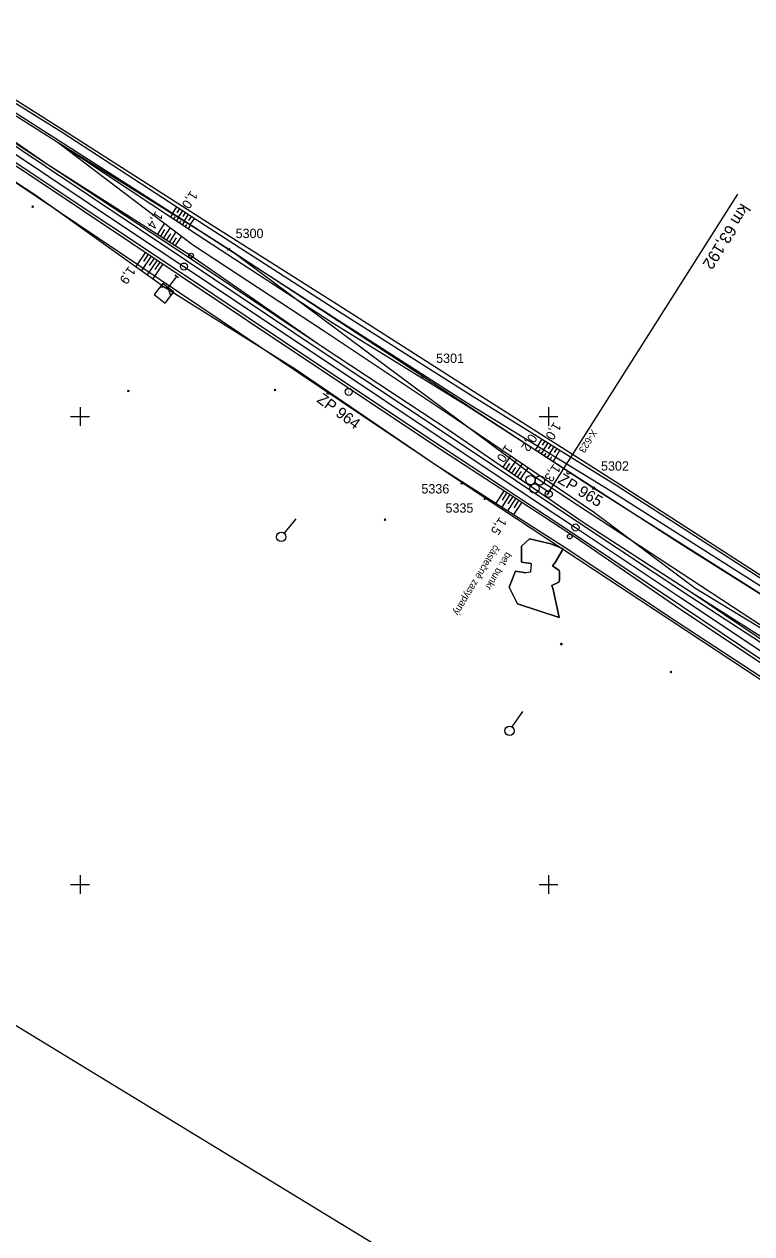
# Model space of a CAD drawing. Extents: x -804899 to -803847, y -1165742 to -1164942.
# Drawn here: x -804511.9 to -804356.6, y -1165474.6 to -1165216.2 of the extents above; entities that cross this region are included whole.
import ezdxf

# ---------------------------------------------------------------- set-up
doc = ezdxf.new("R2010")
doc.units = 0
for name, color, linetype in [('0381KM061-064P - Vrstva 1', 7, 'Continuous'), ('0381KM061-064P - Vrstva 23', 7, 'Continuous'), ('0381KM061-064P - Vrstva 36', 7, 'Continuous'), ('0381KM061-064P - Vrstva 4', 7, 'Continuous'), ('0381KM061-064P - Vrstva 48', 7, 'Continuous'), ('0381KM061-064P - Vrstva 49', 7, 'Continuous'), ('0381KM061-064P - Vrstva 51', 7, 'Continuous'), ('0381KM061-064P - Vrstva 55', 7, 'Continuous'), ('0381KM061-064P - Vrstva 7', 7, 'Continuous'), ('0381KM061-064P - Vrstva 8', 7, 'Continuous'), ('formát', 7, 'Continuous'), ('krizky_1000 - Vrstva 1', 7, 'Continuous'), ('szdc - hran DP', 7, 'Continuous'), ('szdc - szdc_cislo', 7, 'Continuous'), ('szdc - szdc_krizek', 7, 'Continuous'), ('vyt_sit - stávající', 7, 'Continuous')]:
    doc.layers.add(name, color=color, linetype=linetype)

msp = doc.modelspace()

# ---------------------------------------------------------------- linework, layer by layer
at = {"layer": '0381KM061-064P - Vrstva 1'}
msp.add_lwpolyline([(-804619.36, -1165173.74), (-804594.78, -1165190.05), (-804577, -1165201.91), (-804561.16, -1165212.47), (-804538.32, -1165227.67), (-804515.3, -1165243.02), (-804489.41, -1165260.27), (-804477.81, -1165268), (-804447.6, -1165288.14), (-804422.03, -1165305.2), (-804398.19, -1165321.09), (-804394.24, -1165323.73), (-804371.85, -1165338.65), (-804349.9, -1165353.29), (-804326.64, -1165368.8), (-804303.84, -1165384.01), (-804280.33, -1165399.7), (-804257.04, -1165415.23), (-804233.85, -1165430.69)], dxfattribs=at)
at = {"layer": '0381KM061-064P - Vrstva 23'}
msp.add_lwpolyline([(-804404.03, -1165326.13), (-804405.8, -1165327.74), (-804405.76, -1165331.16), (-804403.73, -1165331.39), (-804403.83, -1165333.25), (-804404.81, -1165333.4), (-804407.08, -1165333.06), (-804408.38, -1165336.47), (-804406.6, -1165340), (-804397.73, -1165342.97), (-804399.04, -1165336.98), (-804399.28, -1165336.09), (-804397.81, -1165335.38), (-804397.64, -1165335), (-804397.65, -1165333.2), (-804397.7, -1165332.91), (-804399.15, -1165331.95), (-804398.58, -1165331.24), (-804396.84, -1165328.29), (-804399.49, -1165327.23), (-804404.03, -1165326.13)], dxfattribs=at)
at = {"layer": '0381KM061-064P - Vrstva 36'}
for p, q in [((-804456.41, -1165324.98), (-804453.88, -1165321.88)), ((-804457.04, -1165325.75), (-804457.04, -1165325.75)), ((-804407.75, -1165366.33), (-804405.5, -1165363.02)), ((-804408.31, -1165367.16), (-804408.31, -1165367.16))]:
    msp.add_line(p, q, dxfattribs=at)
for centre in [(-804457.04, -1165325.75), (-804408.31, -1165367.16)]:
    msp.add_circle(centre, 1, dxfattribs=at)
at = {"layer": '0381KM061-064P - Vrstva 4'}
for points in [[(-804755.73, -1165115.93), (-804748.17, -1165116.91), (-804721.25, -1165123.25), (-804698.66, -1165130.22), (-804681.33, -1165136.99), (-804671.47, -1165141.65), (-804648.84, -1165153.36), (-804638.11, -1165160.03), (-804624.48, -1165168.7), (-804602.56, -1165183.07), (-804574.47, -1165201.72), (-804542.72, -1165222.84), (-804507.36, -1165246.55), (-804477.08, -1165266.82), (-804448.75, -1165285.88), (-804421.18, -1165304.15), (-804392.89, -1165323.09), (-804369.85, -1165338.37), (-804348.86, -1165352.04), (-804325.13, -1165367.98), (-804299.32, -1165385.27), (-804266.05, -1165407.31), (-804234.28, -1165428.6)], [(-804755.73, -1165115.93), (-804748.03, -1165116.49), (-804721.05, -1165122.36), (-804698.44, -1165129.77), (-804680.98, -1165136.5), (-804671.21, -1165140.89), (-804648.42, -1165152.46), (-804637.55, -1165159.43), (-804624.04, -1165168.29), (-804602.25, -1165182.38), (-804573.74, -1165201.2), (-804542.46, -1165222.56), (-804507.06, -1165246.03), (-804476.47, -1165266.24), (-804448.31, -1165285.08), (-804421.02, -1165303.1), (-804392.59, -1165322.59), (-804369.41, -1165337.65), (-804348.68, -1165351.59), (-804324.76, -1165367.42), (-804298.9, -1165384.42), (-804265.65, -1165406.5), (-804234.05, -1165428.04)], [(-804626.64, -1165171.43), (-804605.18, -1165186.34), (-804576.91, -1165204.69), (-804544.69, -1165226.09), (-804509.35, -1165249.3), (-804478.87, -1165269.77), (-804450.06, -1165288.98), (-804422.82, -1165307.11), (-804394.42, -1165325.66), (-804371.77, -1165341.24), (-804350.46, -1165355.38), (-804326.73, -1165371.34), (-804301.47, -1165388.34), (-804268.3, -1165410.72), (-804235.74, -1165432.01)], [(-804576.36, -1165204.15), (-804544.19, -1165225.52), (-804508.95, -1165249), (-804478.52, -1165269.18), (-804449.67, -1165288.56), (-804422.62, -1165306.58), (-804394.22, -1165325.33), (-804371.37, -1165340.61), (-804350.54, -1165354.66), (-804326.31, -1165370.81), (-804300.9, -1165387.72), (-804267.8, -1165409.92), (-804235.52, -1165431.44)]]:
    msp.add_lwpolyline(points, dxfattribs=at)
at = {"layer": '0381KM061-064P - Vrstva 48'}
for p, q in [((-804480.29, -1165256.71), (-804479.34, -1165255.26)), ((-804479.28, -1165256.53), (-804478.71, -1165255.67)), ((-804479.02, -1165257.51), (-804478.08, -1165256.08)), ((-804478.01, -1165257.34), (-804477.46, -1165256.49)), ((-804481.97, -1165258.76), (-804483.45, -1165261.08)), ((-804480.25, -1165256.74), (-804480.67, -1165257.37)), ((-804479.78, -1165257.4), (-804480.04, -1165257.79)), ((-804478.97, -1165257.53), (-804479.42, -1165258.2)), ((-804478.52, -1165258.2), (-804478.79, -1165258.61)), ((-804477.7, -1165258.33), (-804478.16, -1165259.03)), ((-804477.74, -1165258.3), (-804476.83, -1165256.9)), ((-804477.25, -1165259.01), (-804477.54, -1165259.44)), ((-804476.43, -1165259.12), (-804476.91, -1165259.86)), ((-804476.74, -1165258.14), (-804476.2, -1165257.3)), ((-804476.47, -1165259.09), (-804475.57, -1165257.71)), ((-804481.95, -1165260.12), (-804482.82, -1165261.48)), ((-804480.77, -1165259.67), (-804482.18, -1165261.89)), ((-804480.72, -1165260.99), (-804481.55, -1165262.29)), ((-804479.57, -1165260.57), (-804480.92, -1165262.69)), ((-804478.37, -1165261.48), (-804479.66, -1165263.5)), ((-804479.5, -1165261.86), (-804480.29, -1165263.1)), ((-804486.06, -1165264.95), (-804488.11, -1165268)), ((-804484.82, -1165265.78), (-804486.89, -1165268.87)), ((-804485.44, -1165265.36), (-804486.47, -1165266.9)), ((-804483.57, -1165266.62), (-804485.67, -1165269.74)), ((-804484.19, -1165266.2), (-804485.24, -1165267.75)), ((-804482.32, -1165267.45), (-804484.45, -1165270.61)), ((-804482.95, -1165267.04), (-804484, -1165268.61)), ((-804402.3, -1165306.36), (-804401.37, -1165304.86)), ((-804401.29, -1165306.16), (-804400.73, -1165305.26)), ((-804401.02, -1165307.14), (-804400.09, -1165305.66)), ((-804402.31, -1165306.35), (-804402.82, -1165307.15)), ((-804401.88, -1165307.07), (-804402.19, -1165307.55)), ((-804401.03, -1165307.14), (-804401.56, -1165307.96)), ((-804400.6, -1165307.87), (-804400.93, -1165308.37)), ((-804399.75, -1165307.92), (-804400.3, -1165308.78)), ((-804400.01, -1165306.94), (-804399.46, -1165306.05)), ((-804399.74, -1165307.93), (-804398.82, -1165306.45)), ((-804398.73, -1165307.73), (-804398.18, -1165306.84)), ((-804398.46, -1165308.71), (-804397.55, -1165307.24)), ((-804409.69, -1165310.87), (-804408.04, -1165308.45)), ((-804409.07, -1165311.29), (-804408.24, -1165310.08)), ((-804408.45, -1165311.72), (-804406.79, -1165309.3)), ((-804407.22, -1165312.57), (-804405.55, -1165310.14)), ((-804399.33, -1165308.66), (-804399.67, -1165309.19)), ((-804398.47, -1165308.71), (-804399.04, -1165309.59)), ((-804407.84, -1165312.14), (-804407, -1165310.93)), ((-804406.6, -1165312.99), (-804405.76, -1165311.77)), ((-804405.98, -1165313.41), (-804404.31, -1165310.98)), ((-804411.18, -1165318.55), (-804409.42, -1165315.86)), ((-804409.92, -1165319.36), (-804408.16, -1165316.68)), ((-804409.84, -1165317.89), (-804408.79, -1165316.27)), ((-804408.65, -1165320.17), (-804406.91, -1165317.5)), ((-804408.58, -1165318.7), (-804407.54, -1165317.09)), ((-804407.39, -1165320.98), (-804405.65, -1165318.32)), ((-804407.32, -1165319.51), (-804406.28, -1165317.91))]:
    msp.add_line(p, q, dxfattribs=at)
at = {"layer": '0381KM061-064P - Vrstva 49'}
for p, q in [((-804509.94, -1165255.38), (-804510.3, -1165255.03)), ((-804509.94, -1165255.03), (-804510.3, -1165255.38)), ((-804489.49, -1165294.74), (-804489.84, -1165294.38)), ((-804489.49, -1165294.38), (-804489.84, -1165294.74)), ((-804458.23, -1165294.57), (-804458.58, -1165294.21)), ((-804458.23, -1165294.21), (-804458.58, -1165294.57)), ((-804434.74, -1165322.21), (-804435.09, -1165321.86)), ((-804434.74, -1165321.86), (-804435.09, -1165322.21)), ((-804397.06, -1165348.83), (-804397.41, -1165348.47)), ((-804397.06, -1165348.47), (-804397.41, -1165348.83)), ((-804373.68, -1165354.74), (-804374.04, -1165354.39)), ((-804373.68, -1165354.39), (-804374.04, -1165354.74))]:
    msp.add_line(p, q, dxfattribs=at)
for points in [[(-804668.09, -1165135.13), (-804646.08, -1165148.91), (-804635.34, -1165155.79), (-804621.98, -1165164.4), (-804599.68, -1165178.86), (-804570.23, -1165197.63), (-804539.04, -1165217.4), (-804503.79, -1165239.32), (-804473.21, -1165259.25), (-804445.02, -1165277.37), (-804416.3, -1165295.6), (-804385.23, -1165314.87), (-804342.84, -1165342.16), (-804322.16, -1165355.5), (-804292.15, -1165374.6), (-804262.58, -1165393.44), (-804234.25, -1165411.43)], [(-804668.53, -1165136.56), (-804646.51, -1165150.38), (-804635.75, -1165157.19), (-804622.88, -1165165.28), (-804600.74, -1165180), (-804571.06, -1165199.05), (-804539.91, -1165219.23), (-804504.85, -1165241.38), (-804474.07, -1165260.59), (-804445.75, -1165278.86), (-804417.38, -1165297.08), (-804386.13, -1165316.29), (-804343.68, -1165343.22), (-804323.05, -1165356.81), (-804293.41, -1165375.48), (-804263.45, -1165394.43), (-804234.68, -1165412.78)], [(-804651.73, -1165158.22), (-804641.24, -1165165.82), (-804629.21, -1165174.28), (-804606.38, -1165188.59), (-804578.69, -1165207.38), (-804546.55, -1165228.41), (-804509.4, -1165252.77), (-804482.02, -1165272.35), (-804454.07, -1165289.87), (-804424.02, -1165310.32)], [(-804621.79, -1165169), (-804602.1, -1165181.9), (-804573.29, -1165200.8), (-804541.65, -1165222.05), (-804507.06, -1165246.03), (-804476.55, -1165265.48), (-804448.31, -1165285.08)], [(-804576.91, -1165204.69), (-804544.69, -1165226.09), (-804509.35, -1165249.3), (-804478.87, -1165269.77), (-804450.06, -1165288.98), (-804422.82, -1165307.11), (-804394.42, -1165325.66), (-804371.77, -1165341.24), (-804350.46, -1165355.38), (-804326.73, -1165371.34), (-804301.47, -1165388.34), (-804268.3, -1165410.72), (-804235.74, -1165432.01)], [(-804504.85, -1165241.38), (-804475.98, -1165263.3)], [(-804504.85, -1165241.38), (-804474.97, -1165261.14)], [(-804474.97, -1165261.14), (-804446.16, -1165279.93), (-804417.55, -1165297.62), (-804371.56, -1165327.37), (-804344.89, -1165344.14), (-804323.3, -1165357.63), (-804293.83, -1165376.15), (-804263.84, -1165395.04), (-804235.23, -1165413.58)], [(-804475.98, -1165263.3), (-804448.01, -1165281.64), (-804419.88, -1165300.43), (-804390.2, -1165320.54), (-804368.79, -1165336.61), (-804347.55, -1165349.48), (-804323.92, -1165365.2), (-804298.45, -1165381.67), (-804264.49, -1165403.75), (-804232.5, -1165426.01)], [(-804448.31, -1165285.08), (-804421.02, -1165303.1), (-804392.59, -1165322.59), (-804369.41, -1165337.65)], [(-804424.02, -1165310.32), (-804397.08, -1165327.6), (-804372.3, -1165344.03), (-804352.55, -1165356.96), (-804329.59, -1165372.88)], [(-804403.73, -1165331.39), (-804405.76, -1165331.16), (-804405.8, -1165327.74), (-804404.03, -1165326.13), (-804399.49, -1165327.23), (-804396.84, -1165328.29), (-804398.58, -1165331.24)], [(-804403.73, -1165331.39), (-804403.83, -1165333.25), (-804404.81, -1165333.4)], [(-804398.58, -1165331.24), (-804399.15, -1165331.95), (-804397.7, -1165332.91), (-804397.65, -1165333.2), (-804397.64, -1165335), (-804397.81, -1165335.38), (-804399.28, -1165336.09), (-804399.04, -1165336.98)], [(-804399.04, -1165336.98), (-804397.73, -1165342.97), (-804406.6, -1165340), (-804408.38, -1165336.47), (-804407.08, -1165333.06), (-804404.81, -1165333.4)], [(-804369.41, -1165337.65), (-804350.13, -1165349.85)]]:
    msp.add_lwpolyline(points, dxfattribs=at)
at = {"layer": '0381KM061-064P - Vrstva 51'}
msp.add_lwpolyline([(-804728.9, -1165105.9), (-804711.54, -1165108.67), (-804704.35, -1165111.8), (-804683.69, -1165124.09), (-804676.95, -1165128.43), (-804667.36, -1165134.41), (-804645.71, -1165148.3), (-804634.7, -1165155.23), (-804621.63, -1165163.62), (-804599.19, -1165178.23), (-804569.67, -1165197.16), (-804538.42, -1165216.77), (-804503.41, -1165238.94), (-804472.82, -1165258.55), (-804444.57, -1165276.4), (-804415.82, -1165294.73), (-804384.7, -1165314.57), (-804342.59, -1165341.72), (-804321.8, -1165355.02), (-804291.77, -1165374.22), (-804262.45, -1165392.96)], dxfattribs=at)
at = {"layer": '0381KM061-064P - Vrstva 55'}
msp.add_lwpolyline([(-804468.27, -1165264.32), (-804426.86, -1165291.43), (-804390.35, -1165315.35), (-804348.41, -1165341.86), (-804327.45, -1165354.94), (-804302.94, -1165371.26), (-804261.01, -1165397.26), (-804213.5, -1165427.44), (-804191.69, -1165441.88), (-804177.28, -1165451.4), (-804169.73, -1165458.18), (-804172.29, -1165470.42), (-804193.11, -1165453.43), (-804217.51, -1165435.77), (-804323.51, -1165365.07), (-804402.46, -1165313.29)], close=True, dxfattribs=at)
at = {"layer": '0381KM061-064P - Vrstva 7'}
for p, q in [((-804476.35, -1165265.63), (-804476.26, -1165265.69)), ((-804481.17, -1165272.51), (-804479.35, -1165270.13)), ((-804478.95, -1165270.43), (-804479.75, -1165269.83)), ((-804395.51, -1165325.63), (-804395.43, -1165325.69))]:
    msp.add_line(p, q, dxfattribs=at)
for points in [[(-804481.17, -1165272.51), (-804482.36, -1165271.6), (-804484.18, -1165273.99), (-804481.8, -1165275.81), (-804479.98, -1165273.42), (-804481.17, -1165272.51)], [(-804480.59, -1165274.22), (-804481.17, -1165272.51), (-804482.97, -1165272.4)]]:
    msp.add_lwpolyline(points, dxfattribs=at)
for centre, radius in [((-804476.3, -1165265.66), 0.5), ((-804477.81, -1165268), 0.75), ((-804394.24, -1165323.73), 0.75), ((-804395.47, -1165325.66), 0.5)]:
    msp.add_circle(centre, radius, dxfattribs=at)
at = {"layer": '0381KM061-064P - Vrstva 8'}
for p, q in [((-804399.91, -1165316.21), (-804359.62, -1165252.51)), ((-804399.91, -1165316.21), (-804402.41, -1165314.55)), ((-804400.33, -1165316.84), (-804399.49, -1165315.59))]:
    msp.add_line(p, q, dxfattribs=at)
for centre in [(-804403.82, -1165313.61), (-804401.85, -1165313.72), (-804402.96, -1165315.38)]:
    msp.add_circle(centre, 1, dxfattribs=at)
at = {"layer": 'formát'}
msp.add_line((-804360.64, -1165523.44), (-804898.57, -1165195.52), dxfattribs=at)
at = {"layer": 'krizky_1000 - Vrstva 1'}
for points in [[(-804502, -1165300), (-804498, -1165300)], [(-804500, -1165298), (-804500, -1165302)], [(-804402, -1165300), (-804398, -1165300)], [(-804400, -1165298), (-804400, -1165302)], [(-804500, -1165398), (-804500, -1165402)], [(-804400, -1165398), (-804400, -1165402)], [(-804502, -1165400), (-804498, -1165400)], [(-804402, -1165400), (-804398, -1165400)]]:
    msp.add_lwpolyline(points, dxfattribs=at)
at = {"layer": 'szdc - hran DP'}
for p, q in [((-804418.46, -1165314.18), (-804552.85, -1165223.84)), ((-804519.76, -1165231.32), (-804468.27, -1165264.32)), ((-804468.27, -1165264.32), (-804426.86, -1165291.43)), ((-804426.86, -1165291.43), (-804390.35, -1165315.35)), ((-804413.53, -1165317.49), (-804418.46, -1165314.18)), ((-804390.35, -1165315.35), (-804348.41, -1165341.86)), ((-804272.3, -1165410.7), (-804413.53, -1165317.49))]:
    msp.add_line(p, q, dxfattribs=at)
at = {"layer": 'szdc - szdc_krizek'}
for p, q in [((-804468.01, -1165264.58), (-804468.54, -1165264.05)), ((-804468.54, -1165264.58), (-804468.01, -1165264.05)), ((-804426.59, -1165291.7), (-804427.13, -1165291.17)), ((-804427.13, -1165291.7), (-804426.59, -1165291.17)), ((-804418.2, -1165314.45), (-804418.73, -1165313.92)), ((-804418.73, -1165314.45), (-804418.2, -1165313.92)), ((-804390.08, -1165315.61), (-804390.62, -1165315.08)), ((-804390.62, -1165315.61), (-804390.08, -1165315.08)), ((-804413.27, -1165317.76), (-804413.8, -1165317.23)), ((-804413.8, -1165317.76), (-804413.27, -1165317.23))]:
    msp.add_line(p, q, dxfattribs=at)
at = {"layer": 'vyt_sit - stávající'}
for p, q in [((-804442.7, -1165294.74), (-804442.61, -1165294.8)), ((-804399.99, -1165316.55), (-804399.91, -1165316.61))]:
    msp.add_line(p, q, dxfattribs=at)
for centre in [(-804442.66, -1165294.77), (-804399.95, -1165316.58)]:
    msp.add_circle(centre, 0.756, dxfattribs=at)

# ---------------------------------------------------------------- texts
at = {"layer": '0381KM061-064P - Vrstva 23'}
for s, p in [('částečně zasypaný', (-804411.6, -1165327.33)), ('bet. bunkr', (-804409.02, -1165328.87))]:
    msp.add_text(s, height=1.5, rotation=239.0639, dxfattribs=at).set_placement(p)
at = {"layer": '0381KM061-064P - Vrstva 48'}
for s, rotation, p in [('1,0', 236.9037, (-804476.36, -1165251.68)), ('1,4', 237.4781, (-804483.81, -1165256.02)), ('1,9', 236.1009, (-804489.6, -1165267.8)), ('1,0', 238.1936, (-804398.79, -1165301.06)), ('0,2', 237.1025, (-804403.93, -1165303.54)), ('1,0', 235.8765, (-804409.09, -1165305.87)), ('1,3', 235.5742, (-804398.89, -1165310.02)), ('1,5', 236.8458, (-804410.41, -1165321.38))]:
    msp.add_text(s, height=2, rotation=rotation, dxfattribs=at).set_placement(p)
at = {"layer": '0381KM061-064P - Vrstva 8'}
for s, height, rotation, p in [('km 63,192', 2.5, 237.6925, (-804358.88, -1165254.34)), ('X-623', 1.5, 237.6921, (-804390.75, -1165302.64))]:
    msp.add_text(s, height=height, rotation=rotation, dxfattribs=at).set_placement(p)
at = {"layer": 'szdc - szdc_cislo'}
for s, p in [('5300', (-804466.79, -1165261.92)), ('5301', (-804423.99, -1165288.59)), ('5302', (-804388.79, -1165311.59)), ('5336', (-804427.13, -1165316.47)), ('5335', (-804421.99, -1165320.57))]:
    msp.add_text(s, height=2, dxfattribs=at).set_placement(p)
at = {"layer": 'vyt_sit - stávající'}
for s, rotation, p in [('ŽP 964', 323.5611, (-804449.64, -1165296.77)), ('ŽP 965', 328.5611, (-804398.21, -1165314.06))]:
    msp.add_text(s, height=2.4, rotation=rotation, dxfattribs=at).set_placement(p)

doc.saveas('drawing.dxf')
